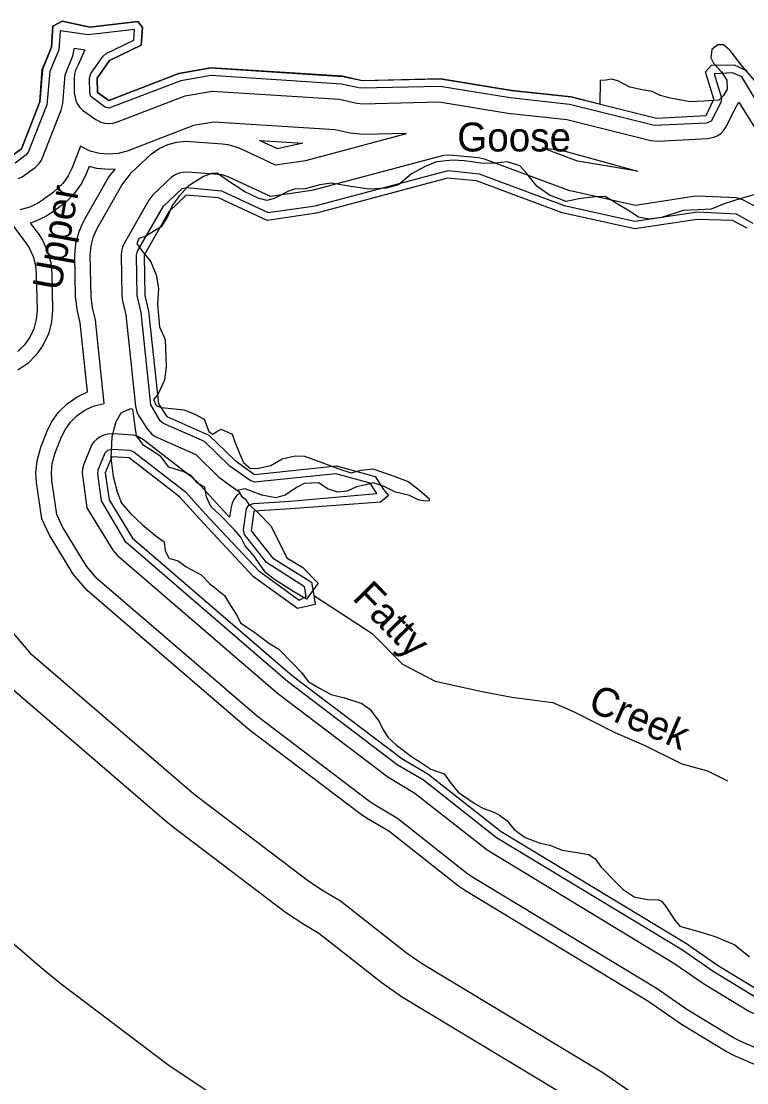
# Model space of a CAD drawing. Extents: x 2532689 to 2764727, y 536648 to 732970.
# Drawn here: x 2615373 to 2619140, y 630300 to 635814 of the extents above; entities that cross this region are included whole.
import ezdxf

# ---------------------------------------------------------------- set-up
doc = ezdxf.new("R2010")
doc.units = 0
for name, color, linetype in [('Exist Boundary Land Use Park State Division NC Parks and Recreation', 7, 'Continuous'), ('Exist Hydrographic Buffer Line', 7, 'Continuous'), ('Exist Hydrographic Creek Double Shore', 7, 'Continuous'), ('Exist Hydrographic Creek Single Shore', 7, 'Continuous'), ('Exist Hydrographic Creek Single Shore Label', 7, 'Continuous'), ('Exist Hydrographic River Shore', 7, 'Continuous'), ('Exist Hydrographic River Shore Label', 7, 'Continuous')]:
    doc.layers.add(name, color=color, linetype=linetype)

msp = doc.modelspace()

# ---------------------------------------------------------------- linework, layer by layer
at = {"layer": 'Exist Boundary Land Use Park State Division NC Parks and Recreation'}
for points in [[(2618596.3, 635457.1), (2618533.8, 635470.8), (2618470.8, 635504.1), (2618438, 635512.5), (2618408.7, 635508.1), (2618379.6, 635506.9), (2618377.7, 635383.9), (2618227.4, 635421.1), (2617918.4, 635455.1), (2617550.5, 635515.1), (2617142.5, 635505.1), (2617042.4, 635528.1), (2616357.5, 635572.1), (2616191.5, 635543), (2615827.5, 635403), (2615768.4, 635443.1), (2615767.4, 635519.1), (2615831.6, 635610), (2615996.4, 635689), (2616003.4, 635781.1), (2615977.6, 635813), (2615728.4, 635783.1), (2615585.5, 635814.1), (2615536.5, 635789.1), (2615530.6, 635680.1), (2615482.6, 635563.1), (2615469.5, 635395), (2615374.5, 635152.1), (2615317.5, 635110.1)], [(2619186, 635500.4), (2619118, 635579), (2619052.8, 635664.1), (2619018.9, 635692), (2618989.8, 635690.8), (2618958.2, 635666.8), (2618953.5, 635624.4), (2618967.7, 635595.7), (2619008.5, 635551.8), (2619036.3, 635507.4), (2619038, 635462), (2619019.9, 635428.8), (2618994.9, 635404.9), (2618917.2, 635398.6), (2618845.6, 635395.7), (2618744.4, 635414.3), (2618691.4, 635428.4), (2618648.6, 635449.5), (2618596.3, 635457.1)], [(2619177.4, 634911.7), (2619110, 634892.7), (2619023.2, 634866.4), (2618956, 634837.8), (2618888.1, 634835), (2618810, 634831.8), (2618778, 634820.7), (2618697.8, 634794.8), (2618633, 634785.7), (2618577.4, 634796.4), (2618530.7, 634827), (2618476.6, 634860.2), (2618404.6, 634904.2), (2618354.8, 634902.2), (2618278.7, 634893.2), (2618203, 634878.4), (2618116.7, 634910.1), (2618050.3, 634957.3), (2617997.8, 635022.7), (2617961.1, 635062.2), (2617898.5, 635083.2), (2617831.3, 635077.6), (2617772.8, 635075.2), (2617672.3, 635088.7), (2617613.5, 635092.2), (2617528.8, 635083), (2617471, 635060), (2617399.2, 635022), (2617331.3, 634963.5), (2617267.6, 634946.2), (2617179.6, 634942.6), (2617085.1, 634956.4), (2616981.7, 634972.8), (2616923.5, 634964.5), (2616848, 634943.9), (2616792.3, 634941.7), (2616760.5, 634931.6), (2616685.8, 634893.4), (2616647.9, 634883), (2616603.4, 634895.9), (2616534.7, 634928.3), (2616444.5, 634986.3), (2616389.9, 635025.1), (2616360.8, 635024), (2616320.2, 635007.6), (2616240.3, 634957.4), (2616192.5, 634905.7), (2616156.2, 634857.2), (2616132.2, 634797.6), (2616099.2, 634746.4), (2616015.9, 634696.1), (2615984.4, 634686)], [(2615984.4, 634686), (2615973.5, 634659.2), (2616001.6, 634619.2), (2616044.8, 634568.2), (2616074, 634496), (2616085.9, 634426.1), (2616080.3, 634343.7), (2616090.8, 634226.8), (2616120.1, 634160.6), (2616125.4, 634019.9), (2616116.8, 633949.2), (2616081.5, 633874.4), (2616061, 633850.3), (2616061, 633846), (2616074.2, 633818.3), (2616099, 633807.2), (2616135.5, 633804.6), (2616216.5, 633795.8), (2616274.1, 633773.9), (2616323.5, 633747.6), (2616346.3, 633683.9), (2616367, 633668.6), (2616386.7, 633681.6), (2616410.4, 633694.7), (2616468.1, 633668.7), (2616481.8, 633628.9), (2616508.5, 633565.3), (2616526.5, 633521.6), (2616564, 633490.9), (2616604.2, 633492.5), (2616668.2, 633507.2), (2616727.5, 633541.9), (2616795.5, 633556.8), (2616843.9, 633554.7), (2616934.2, 633522), (2617040.8, 633481.9), (2617085.7, 633467.6), (2617137.8, 633481.8), (2617198.1, 633488.3), (2617304.5, 633452.2), (2617382.6, 633423), (2617432.4, 633384.7), (2617491.1, 633334.6), (2617491.5, 633322.4), (2617471.2, 633321.6), (2617434.7, 633328.3), (2617389.6, 633350.6), (2617316, 633367.8), (2617258.3, 633397.8), (2617200.9, 633415.7), (2617160.9, 633406), (2617113, 633396), (2617065.6, 633373.9), (2617017.2, 633367.9), (2616964.1, 633385.9), (2616918.2, 633416.4), (2616841.7, 633413.3), (2616802.3, 633391.5), (2616743.2, 633352.7), (2616695.3, 633338.7), (2616622.3, 633351.9), (2616535.9, 633384.8), (2616500.1, 633379.2), (2616504.6, 633367.3), (2616517.3, 633347.7), (2616538.2, 633332.3), (2616555.4, 633304.7), (2616601.6, 633262.2), (2616669, 633192.3), (2616717.2, 633097.3), (2616752.5, 633026.1), (2616835.3, 632976.9), (2616915.3, 632895.4), (2616854, 632812.1), (2616787.7, 632849.8), (2616688.3, 632914.4), (2616642.6, 632948.9), (2616612.4, 632992.1), (2616582.5, 633035.4), (2616535.7, 633090), (2616514, 633133.5), (2616480, 633172.5), (2616404.3, 633250.2), (2616358, 633292.7), (2616335.8, 633344.4), (2616325.8, 633392.4), (2616288.4, 633415.1), (2616254.8, 633454.1), (2616217.5, 633472.8), (2616139.8, 633498), (2616097.3, 633552.8), (2616010, 633609.8), (2615971.8, 633660.8), (2615960.8, 633732.9), (2615954.4, 633789.2), (2615952.2, 633798), (2615937.8, 633800.7), (2615890.2, 633778.6), (2615863.8, 633733), (2615842.7, 633655.5)], [(2615842.7, 633655.5), (2615839, 633546.3), (2615851.1, 633449.9), (2615870.5, 633370), (2615892.9, 633310.3), (2615939.4, 633259.7), (2616002.6, 633197.6), (2616073.5, 633139.9), (2616115.2, 633109.3), (2616120.9, 633065.1), (2616138.8, 633025.5), (2616187.8, 633011.3), (2616229.2, 632980.7), (2616307.7, 632939.4), (2616350, 632892.7), (2616429.3, 632831.3), (2616459.5, 632780.1), (2616493.9, 632724.9), (2616511.7, 632689.2), (2616545, 632666.4), (2616586.2, 632639.8), (2616657.3, 632586.1), (2616711.1, 632552), (2616782.8, 632478.2), (2616829, 632431.6), (2616863.2, 632384.5), (2616921, 632350.5), (2616983, 632316.7), (2617052.3, 632299.3), (2617142.3, 632270.6), (2617183.9, 632240), (2617231.1, 632177.3), (2617252.8, 632133.8), (2617278.8, 632094.4), (2617320.5, 632055.8), (2617399.8, 631994.4), (2617453.8, 631960.2), (2617499.3, 631929.8), (2617569, 631904.3), (2617603.2, 631857.2), (2617641.6, 631810.3), (2617724.4, 631753.1), (2617769.9, 631726.7), (2617831.5, 631704.9), (2617856.3, 631689.8), (2617893.8, 631663), (2617931.9, 631616.2), (2617990.2, 631574.1), (2618068.1, 631544.9), (2618117.1, 631534.8), (2618182.5, 631509.2), (2618259.8, 631496.2), (2618320.7, 631486.5), (2618353.9, 631463.6), (2618384.1, 631420.4), (2618464, 631338.9), (2618497.7, 631303.9), (2618555.7, 631265.9), (2618625, 631252.5), (2618681.4, 631250.7), (2618698, 631243.4), (2618719.3, 631215.9), (2618766.5, 631145.2), (2618791.9, 631113.9), (2618828.8, 631103.3), (2618914.8, 631078.5), (2618984.3, 631057.1), (2619078.8, 631016.5), (2619153.8, 630954.9)]]:
    msp.add_lwpolyline(points, dxfattribs=at)
at = {"layer": 'Exist Hydrographic Buffer Line'}
for points in [[(2619263.3, 635279.6), (2619113.9, 635525.5), (2619066.3, 635546.8), (2618970.5, 635540.9), (2619009.1, 635415.6), (2619005.6, 635391.5), (2618955.4, 635294.4), (2618931.8, 635285), (2618661.9, 635272.4), (2618220.6, 635381.9), (2617912, 635415.4), (2617547.9, 635475.4), (2617133.9, 635466.5), (2617036.7, 635488), (2616359.8, 635532), (2616202.3, 635503.9), (2615827.5, 635363.1), (2615804.9, 635370.1), (2615733.8, 635423.4), (2615728.4, 635442.9), (2615727.4, 635518.8), (2615734.8, 635541.8), (2615798.8, 635633), (2615814.2, 635646.1), (2615958.3, 635715.1), (2615960.6, 635770.7), (2615720.2, 635744.1), (2615575.3, 635763.4), (2615567.5, 635664.8), (2615522, 635553.8), (2615506.8, 635380.6), (2615411.6, 635137), (2615397.9, 635119.3), (2615340.9, 635077.6)], [(2615358.5, 634997.2), (2615377.4, 635006), (2615445.3, 635054.8), (2615466.4, 635074.5), (2615478.5, 635091.6), (2615581.2, 635351.6), (2615589.2, 635386), (2615600.7, 635535), (2615641.5, 635634.4), (2615650.3, 635673.4), (2615703.4, 635665.8), (2615669.2, 635587.7), (2615654.8, 635559.9), (2615649.3, 635539.7), (2615647.5, 635518.8), (2615648.5, 635441.8), (2615655.7, 635402.3), (2615664.5, 635383.4), (2615676.6, 635366.2), (2615691.3, 635351.5), (2615759.8, 635304), (2615786.5, 635290.3), (2615806.8, 635284.9), (2615827.5, 635283.1), (2615848.2, 635284.9), (2615868.5, 635290.3), (2616223.9, 635426.5), (2616364.3, 635451.6), (2617025.6, 635408.6), (2617116.4, 635388.4), (2617145.6, 635385.6), (2617542.3, 635395.2), (2617899.1, 635336.5), (2618206.5, 635302.9), (2618642.6, 635194.8), (2618678.1, 635191.4), (2618936.1, 635205.2), (2618970.5, 635212.2), (2618989.6, 635221.1), (2619006.8, 635233.1), (2619021.6, 635247.9), (2619033.7, 635265), (2619077.8, 635357), (2619098.3, 635394.4), (2619195.1, 635238.1)], [(2615557.6, 633251.5), (2615532.2, 633429), (2615529.5, 633468.5), (2615533.9, 633517.1), (2615549.4, 633572.3), (2615582.9, 633655.6), (2615600.3, 633691.8), (2615628.2, 633731.9), (2615662.8, 633766.4), (2615702.8, 633794.4), (2615747.1, 633815), (2615803.5, 633828.1), (2615757.8, 634261.6), (2615742.8, 634325.9), (2615735.4, 634384.3), (2615731.5, 634599.5), (2615735.8, 634648.2), (2615748.5, 634695.3), (2615768, 634738), (2615896, 634963.1), (2615946.4, 635027.6), (2616049.6, 635124.9), (2616089.5, 635152.9), (2616133.8, 635173.6), (2616181, 635186.2), (2616229.6, 635190.5), (2616251.3, 635189.6), (2616418.2, 635176.7), (2616445.1, 635173.3), (2616492.3, 635160.6), (2616514.8, 635151.3), (2616692.2, 635068.6), (2616850.3, 635091.2), (2617373.8, 635231.1), (2617149.3, 635225.6), (2617081.8, 635232.1), (2617002.8, 635249.7), (2616373.3, 635290.6), (2616266.9, 635271.7), (2615923.2, 635140), (2615876.1, 635127.3), (2615827.5, 635123), (2615779.1, 635127.3), (2615731.7, 635140), (2615680.3, 635165.1), (2615635.1, 635049.9), (2615616.9, 635011.6), (2615589, 634971.6), (2615539.8, 634925.6), (2615482.8, 634884), (2615457.6, 634867.4), (2615413.3, 634846.8), (2615365.9, 634834.2)], [(2616704.5, 635151.1), (2616610.2, 635195.1), (2616835.1, 635180.5), (2616704.5, 635151.1)], [(2618572.3, 635035.2), (2618261, 635087.9), (2618078.1, 635156.1), (2618178.6, 635145), (2618572.3, 635035.2)], [(2619201.6, 634843.2), (2619122.7, 634885), (2619087.4, 634897.1), (2618886.2, 634904.6), (2618864.5, 634903.2), (2618562.7, 634857.4), (2618215.5, 634934), (2617778.6, 635096.9), (2617747.4, 635104), (2617597.3, 635117.7), (2617565.7, 635116.3), (2616882.5, 634934.1), (2616667.8, 634903.4), (2616447.4, 635006.3), (2616417.2, 635015.7), (2616238.8, 635030.1), (2616208.7, 635028.6), (2616188.6, 635023.2), (2616169.5, 635014.4), (2616152.3, 635002.4), (2616056.7, 634911.7), (2616035.2, 634884.1), (2615907.3, 634658.9), (2615898.8, 634640.6), (2615893.3, 634620.4), (2615891.5, 634599.5), (2615895.6, 634387.3), (2615898.8, 634362.3), (2615916.1, 634288.2), (2615966.1, 633814), (2615972.5, 633785.5), (2615981.3, 633766.6), (2616028, 633694.8), (2616051.2, 633668.6), (2616068.6, 633656.5), (2616279.2, 633563.2), (2616399.8, 633445.9), (2616509.9, 633366.3), (2616488.6, 633347), (2616476.5, 633329.9), (2616467.9, 633310.9), (2616462.3, 633290.6), (2616455.2, 633237.3), (2616386.9, 633310.1), (2616284.5, 633423.4), (2616269, 633437.8), (2616007.1, 633640.6), (2615974.5, 633658.5), (2615954.2, 633663.9), (2615850.9, 633671.6), (2615822, 633670), (2615801.9, 633664.6), (2615782.8, 633655.8), (2615765.6, 633643.8), (2615750.8, 633629), (2615738.7, 633611.9), (2615698.1, 633513), (2615691.3, 633489.3), (2615689.5, 633468.5), (2615714.1, 633287)], [(2615479.7, 633229.5), (2615453.1, 633417.8), (2615449.6, 633468.5), (2615455.1, 633531), (2615475.2, 633602), (2615508.4, 633685.3), (2615531, 633731.8), (2615567.1, 633783.2), (2615611.4, 633827.6), (2615662.8, 633863.6), (2615716.6, 633889.9), (2615678.8, 634248.2), (2615665.1, 634307.8), (2615655.4, 634382.8), (2615651.6, 634599.5), (2615657.1, 634662), (2615673.3, 634722.7), (2615698.5, 634777.4), (2615826.5, 635002.6), (2615860.3, 635045.9), (2615827.5, 635043.1), (2615764.9, 635048.6), (2615725, 635059.3), (2615710, 635020.8), (2615686.2, 634971.6), (2615650.3, 634920.2), (2615606, 634875.9), (2615587, 634861), (2615530, 634819.4), (2615497.6, 634798.2), (2615440.8, 634771.6), (2615419.6, 634766), (2615460.4, 634711.5), (2615483.2, 634676.7), (2615509.7, 634619.8), (2615526.1, 634559.2), (2615531.6, 634504.5), (2615535.5, 634312.9), (2615530, 634250.4), (2615513.8, 634189.8), (2615487.3, 634132.9), (2615451.2, 634081.5), (2615406.9, 634037.1), (2615355.5, 634001.2)], [(2615790, 633322.5), (2615770.1, 633462.9), (2615772.3, 633483.3), (2615808, 633571.8), (2615822.8, 633586.5), (2615845.5, 633591.8), (2615936.4, 633585.7), (2615958.1, 633577.4), (2616225.3, 633369.8), (2616328, 633255.9), (2616606.1, 632958.5), (2616816.7, 632806.5), (2616852.3, 632825.3), (2616844.1, 632876.7), (2616646.3, 633002.7), (2616531.8, 633147.5), (2616526.7, 633172.9), (2616543.1, 633283.5), (2616554.8, 633300.5), (2616578.4, 633309.8), (2616769.9, 633320.8), (2617219.8, 633360.9), (2617185.3, 633415.1), (2617006.3, 633463.4), (2616584.5, 633420.5), (2616561.6, 633427.8), (2616455.6, 633503.2), (2616324.7, 633630.6), (2616112.5, 633723.9), (2616095.1, 633738.6), (2616045.5, 633822.4), (2615995, 634301.6), (2615975.5, 634388.9), (2615971.4, 634599.5), (2615976.8, 634619.3), (2616112.1, 634853.8), (2616209.5, 634945.1), (2616232.5, 634950.3), (2616413.5, 634933.8), (2616655.5, 634820.9), (2616898.5, 634855.6), (2617590.1, 635037.9), (2617750.5, 635022.1), (2618192.8, 634857.1), (2618559.8, 634776.1), (2618883.8, 634824.6), (2619085.4, 634814.3), (2619172.1, 634765.2)], [(2615276.5, 634824.7), (2615396.3, 634663.7), (2615413.9, 634636.7), (2615434.4, 634592.4), (2615447.3, 634545.3), (2615451.4, 634502.8), (2615455.5, 634312.9), (2615451.2, 634264.3), (2615438.5, 634217.2), (2615418, 634172.9), (2615389.9, 634132.9), (2615355.5, 634098.4)], [(2621355.5, 629781.7), (2621122.3, 629870.8), (2620821.5, 630050.1), (2620748.7, 630113.2), (2620173.2, 630430.9), (2619919.3, 630523.3), (2619511.7, 630601), (2619195.9, 630738.6), (2618966, 630878.5), (2618805.9, 630989.5), (2617840.9, 631573.3), (2617462, 631871.4), (2617325.4, 631952.4), (2616755.6, 632384.2), (2615916.3, 633108.7), (2615790, 633322.5)], [(2615714.1, 633287), (2615848, 633067), (2615872.2, 633038.5), (2616703.3, 632323.6), (2617277, 631888.7), (2617416.6, 631805.2), (2617791.5, 631510.4), (2618762.4, 630922.3), (2618920.1, 630812.7), (2619154.5, 630670.3), (2619479.9, 630527.6), (2619505.5, 630519.7), (2619898, 630445.9), (2620139.9, 630357.8), (2620702.8, 630047.3), (2620769.2, 629989.7), (2620786.5, 629977.2), (2621081.5, 629801.9), (2621100.2, 629793)], [(2619384.1, 630307.4), (2619073.3, 630442.6), (2619029.6, 630465.1), (2618801.8, 630603.6), (2618783.5, 630615.6), (2618631.6, 630720.9), (2617679.3, 631296.6), (2617643.2, 631321.7), (2617280.9, 631606.8), (2617166.3, 631674.5), (2617132.4, 631697.3), (2616564.2, 632127.5), (2616546.8, 632141.6), (2615715.7, 632856.6), (2615642.9, 632942.2), (2615517.9, 633148.1), (2615479.7, 633229.5)], [(2615711.2, 632983.8), (2615587, 633188.1), (2615557.6, 633251.5)], [(2617451.7, 630920), (2617370.9, 630975.9), (2617031.6, 631242.9), (2616942.4, 631295.8), (2616866.7, 631346.5), (2616298.5, 631776.7), (2616259.7, 631808.1), (2615428.9, 632523), (2615267.3, 632713.3), (2615136.7, 632928.1), (2615052.5, 633108.9)], [(2614889.8, 632986.1), (2614963.6, 632828.1), (2614975.5, 632808), (2615096.5, 632609.3), (2615298.2, 632371.3), (2616129.3, 631656.4), (2616177.9, 631617.3), (2616745.9, 631187.1), (2616840.4, 631123.7), (2616918.4, 631077.6), (2617247.3, 630818.7), (2617348.2, 630748.9), (2618283.4, 630183.6), (2618418.3, 630089.8), (2618469.4, 630056.6), (2618697.4, 629918.1), (2618818, 629855.7), (2619129, 629720.5), (2619342.7, 629654.9)], [(2619416.1, 630380.8), (2619105.2, 630516), (2619071.4, 630533.5), (2618828.8, 630681.3), (2618675.2, 630788), (2617720.9, 631365.1), (2617692.4, 631384.6), (2617326, 631672.9), (2617207.1, 631743.3), (2617180.6, 631761.1), (2616599.1, 632202.3), (2615768, 632917.2), (2615711.2, 632983.8)], [(2612841.3, 631310.7), (2613188.5, 631280.4), (2613405.8, 631292.2), (2613787.8, 631333.9), (2613917.8, 631352.5), (2614254.5, 631442.8), (2614570.5, 631590.1), (2614630.2, 631632), (2614646.2, 631613.3), (2615477.3, 630898.4), (2615574, 630820.1), (2616142, 630389.9), (2616331.1, 630262.9), (2616352, 630250.6), (2616628.8, 630032.8), (2616830.8, 629893.1), (2617739, 629344.1), (2617848.1, 629268.3), (2617950.4, 629202), (2618178.4, 629063.4), (2618419.3, 628938.6), (2618730.4, 628803.4), (2619157.7, 628672.2)], [(2619208.8, 629904), (2618897.7, 630039.1), (2618801.4, 630089.1), (2618573.3, 630227.6), (2618532.3, 630254.1), (2618392.1, 630351.5), (2617451.7, 630920)]]:
    msp.add_lwpolyline(points, dxfattribs=at)
at = {"layer": 'Exist Hydrographic Creek Double Shore'}
for points in [[(2615317.5, 635109.9), (2615374.5, 635151.6), (2615469.5, 635395.2), (2615482.4, 635563.1), (2615530.6, 635680), (2615536.5, 635788.6), (2615585.5, 635813.6), (2615728.4, 635783.2), (2615977.6, 635813), (2616003.4, 635781.2), (2615996.4, 635689), (2615831.6, 635610.1), (2615767.4, 635518.8), (2615768.4, 635443.4), (2615827.5, 635403.1), (2616191.5, 635542.6), (2616357.5, 635572.3), (2617042.6, 635527.7), (2617142.5, 635505.5), (2617550.5, 635515.5), (2617918.6, 635454.9), (2618227.6, 635421.3), (2618671.6, 635311.2), (2618929.5, 635325), (2618969.5, 635408.7), (2618925.6, 635551.4), (2618957.6, 635585.5), (2619074.5, 635586.9), (2619141.5, 635556.8)], [(2619141.5, 634739.3), (2619066.7, 634778.9), (2618882.6, 634784.6), (2618558.6, 634735.4), (2618181.5, 634818.6), (2617736.5, 634984.5), (2617586.6, 634998.2), (2616906.5, 634816.3), (2616649.5, 634779.6), (2616396.5, 634897.5), (2616229.6, 634910.5), (2616139.6, 634824.7), (2616011.4, 634599.5), (2616015.5, 634389.6), (2616034.6, 634308.2), (2616085.2, 633826.6)], [(2616085.2, 633826.6), (2616128.5, 633760.5), (2616347.5, 633664.3), (2616483.4, 633531.9), (2616584.5, 633460.5)], [(2615842.9, 633551.8), (2615809.4, 633468.5), (2615829.5, 633328.2)], [(2616195.6, 633343), (2615933.5, 633545.7), (2615842.9, 633551.8)], [(2616584.5, 633460.5), (2617009.6, 633503.9), (2617210.6, 633449.6), (2617253.6, 633382.4), (2617279.7, 633350.7), (2617238.7, 633316.2), (2616772.6, 633280.9), (2616580.6, 633269.8)], [(2616891.9, 632831.7), (2616899.5, 632783.7), (2616807.6, 632763.6), (2616579.6, 632928.3), (2616298.5, 633228.9), (2616195.6, 633343)], [(2616580.6, 633269.8), (2616566.5, 633167.5), (2616677.6, 633027.5), (2616880.6, 632901.1), (2616891.9, 632831.7)]]:
    msp.add_lwpolyline(points, dxfattribs=at)
at = {"layer": 'Exist Hydrographic Creek Single Shore'}
msp.add_lwpolyline([(2616891.9, 632831.7), (2617064.6, 632718.8), (2617195.6, 632634.3), (2617353.3, 632474.2), (2617522.4, 632386.3), (2617766.7, 632333.4), (2617920.7, 632303.3), (2618132.7, 632276.1), (2618247.1, 632225.6), (2618456, 632120.1), (2618604.9, 632056), (2618803.6, 631956.4), (2618935.9, 631920.1), (2619040.4, 631869.4)], dxfattribs=at)
at = {"layer": 'Exist Hydrographic River Shore'}
msp.add_lwpolyline([(2615829.5, 633328.2), (2615950.5, 633129.5), (2616781.6, 632414.5), (2617349.6, 631984.3), (2617484.5, 631904.4), (2617865.7, 631604.7), (2618827.6, 631023.1), (2618988.8, 630911.3), (2619216.6, 630772.8), (2619527.7, 630637.6), (2619929.8, 630562), (2620189.8, 630467.4), (2620771.7, 630146.2), (2620847.8, 630080.4), (2621142.8, 629905.1), (2621369.8, 629819.1), (2621729.7, 629751.5), (2622014.7, 629681.1), (2622191.9, 629602.8), (2622471.8, 629325.2), (2622581.9, 629260.7), (2622916.8, 629192.2), (2623000.8, 629152.8), (2623187.8, 628979.8)], dxfattribs=at)

# ---------------------------------------------------------------- texts
at = {"layer": 'Exist Hydrographic Creek Single Shore Label'}
msp.add_text('Goose', height=150, dxfattribs=at).set_placement((2617636.8, 635137.6))
for s, rotation, p in [('Upper', 79.7841, (2615578, 634409.2)), ('Fatty', 314.5655, (2617087.3, 632814.4)), ('Creek', 336.6945, (2618308.7, 632237.2))]:
    msp.add_text(s, height=150, rotation=rotation, dxfattribs=at).set_placement(p)
at = {"layer": 'Exist Hydrographic River Shore Label'}
msp.add_text('P         A         M         L         I         C         O', height=840, rotation=340.2658, dxfattribs=at).set_placement((2610107.5, 629929.9))

doc.saveas('drawing.dxf')
